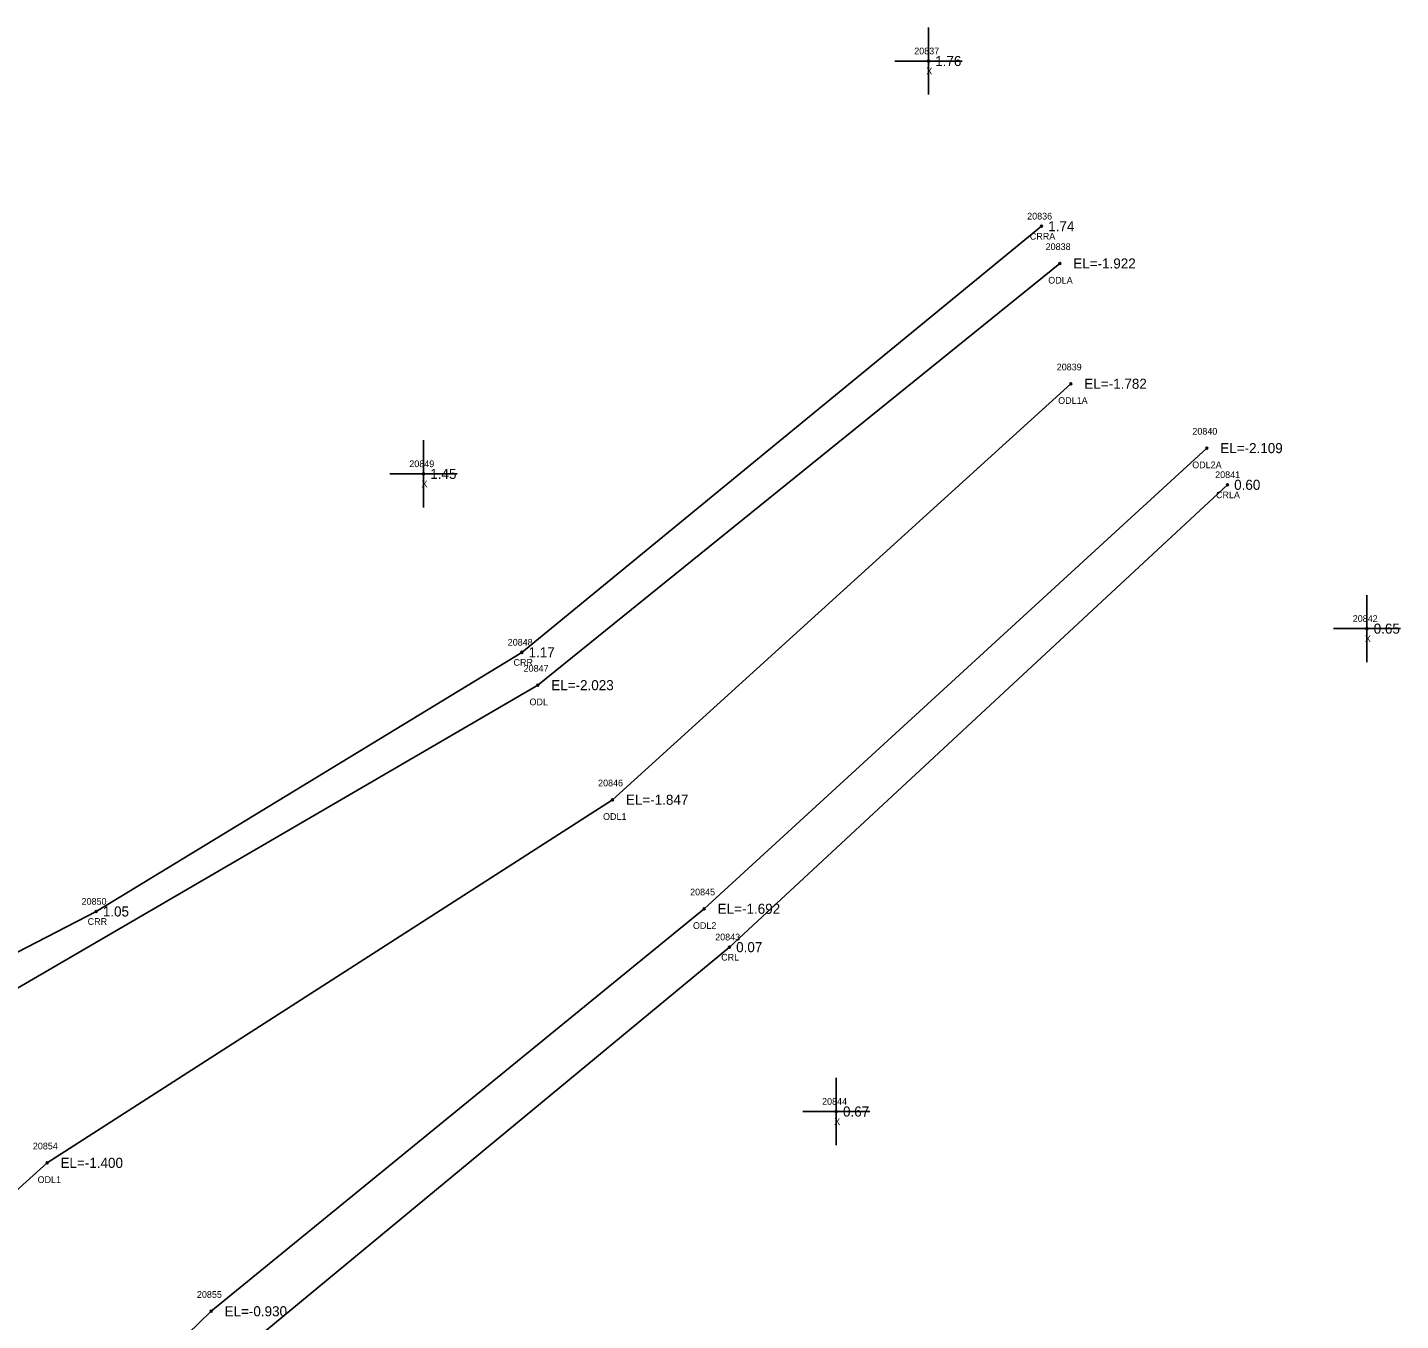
# Model space of a CAD drawing. Extents: x 2608745 to 2610333, y 641917 to 643463.
# Drawn here: x 2609764.9 to 2609969.6, y 642851.5 to 643044.2 of the extents above; entities that cross this region are included whole.
import ezdxf

# ---------------------------------------------------------------- set-up
doc = ezdxf.new("R2010")
doc.units = 0
for name, color, linetype in [('RD_EX_H2O', 7, 'Continuous'), ('RD_EX_H2O_txCode', 7, 'Continuous'), ('RD_EX_Misc', 7, 'Continuous'), ('RD_EX_Misc_txCode', 7, 'Continuous'), ('RD_EX_TX_H2O_ELEV', 7, 'Continuous'), ('RD_EX_TX_Misc_ELEV', 7, 'Continuous'), ('RD_SMD_Locator', 7, 'Continuous')]:
    doc.layers.add(name, color=color, linetype=linetype)

msp = doc.modelspace()

# ---------------------------------------------------------------- linework, layer by layer
at = {"layer": 'RD_EX_H2O'}
for points in [[(2609916.07, 643014.59), (2609838.61, 642951.08), (2609775.14, 642912.46), (2609751.54, 642900.29), (2609699.49, 642867.34), (2609668.6, 642867.67), (2609610.85, 642947.01)], [(2609918.81, 643009.04), (2609840.99, 642946.19), (2609752.78, 642894.89), (2609679.02, 642833.68), (2609605.53, 642770.83), (2609557.42, 642733.27), (2609539.43, 642701.73), (2609511.68, 642671.53), (2609423.05, 642632.06), (2609369.55, 642600.24), (2609327.57, 642579.96), (2609257.07, 642528.8), (2609194.6, 642443.8), (2609156.56, 642341.27)], [(2609920.46, 642991.11), (2609852.12, 642929.11), (2609767.83, 642874.99), (2609693.3, 642807.6), (2609634.08, 642753.09), (2609556.79, 642686.91), (2609524.97, 642657.54), (2609444.81, 642602.16), (2609373.09, 642552.33), (2609285.68, 642492.71), (2609230.49, 642411.33), (2609205.38, 642280.88)], [(2609940.72, 642981.52), (2609865.8, 642912.86), (2609792.29, 642852.87), (2609723.77, 642786.36), (2609663.25, 642717.18), (2609610.37, 642689.46), (2609581.45, 642670.47), (2609545.26, 642637.18), (2609509.19, 642582.86), (2609482.73, 642569.2), (2609408.72, 642506.3), (2609370.25, 642508.5), (2609327.7, 642455.81), (2609283.83, 642369.21), (2609262.12, 642251.22)], [(2609943.79, 642976.05), (2609869.55, 642907.14), (2609797.73, 642847.7), (2609725.24, 642780.75), (2609667.97, 642714.2), (2609673.28, 642700.22), (2609713.56, 642689.91), (2609733.33, 642661.98), (2609719.28, 642638.68), (2609663.61, 642631.91), (2609659.09, 642626.02), (2609711.84, 642571.44), (2609760.21, 642528.21), (2609792.62, 642516.23), (2609800.76, 642528.12), (2609797.45, 642563.99), (2609816.12, 642605.87)]]:
    msp.add_lwpolyline(points, dxfattribs=at)
at = {"layer": 'RD_EX_Misc'}
for p, q in [((2609899.22, 643034.21), (2609899.22, 643044.21)), ((2609894.22, 643039.21), (2609904.22, 643039.21)), ((2609823.95, 642972.68), (2609823.95, 642982.68)), ((2609818.95, 642977.68), (2609828.95, 642977.68)), ((2609964.59, 642949.61), (2609964.59, 642959.61)), ((2609959.59, 642954.61), (2609969.59, 642954.61)), ((2609885.48, 642877.64), (2609885.48, 642887.64)), ((2609880.48, 642882.64), (2609890.48, 642882.64))]:
    msp.add_line(p, q, dxfattribs=at)
at = {"layer": 'RD_SMD_Locator'}
for centre in [(2609899.22, 643039.21), (2609916.07, 643014.59), (2609918.81, 643009.04), (2609920.46, 642991.11), (2609940.72, 642981.52), (2609823.95, 642977.68), (2609943.79, 642976.05), (2609964.59, 642954.61), (2609838.61, 642951.08), (2609840.99, 642946.19), (2609852.12, 642929.11), (2609775.14, 642912.46), (2609865.8, 642912.86), (2609869.55, 642907.14), (2609885.48, 642882.64), (2609767.83, 642874.99), (2609792.29, 642852.87)]:
    msp.add_circle(centre, 0.15, dxfattribs=at)

# ---------------------------------------------------------------- texts
at = {"layer": 'RD_EX_H2O_txCode'}
for s, p in [('20836', (2609913.93, 643015.59)), ('CRRA', (2609914.33, 643012.59)), ('20838', (2609916.69, 643011.04)), ('ODLA', (2609917.08, 643006.04)), ('20839', (2609918.34, 642993.11)), ('ODL1A', (2609918.56, 642988.11)), ('20840', (2609938.56, 642983.52)), ('ODL2A', (2609938.54, 642978.52)), ('20841', (2609941.96, 642977.05)), ('CRLA', (2609942.08, 642974.05)), ('20848', (2609836.5, 642952.08)), ('CRR', (2609837.36, 642949.08)), ('20847', (2609838.87, 642948.19)), ('ODL', (2609839.75, 642943.19)), ('20846', (2609849.97, 642931.11)), ('ODL1', (2609850.71, 642926.11)), ('20845', (2609863.69, 642914.86)), ('20850', (2609772.98, 642913.46)), ('CRR', (2609773.88, 642910.46)), ('ODL2', (2609864.11, 642909.86)), ('20843', (2609867.43, 642908.14)), ('CRL', (2609868.32, 642905.14)), ('20854', (2609765.71, 642876.99)), ('ODL1', (2609766.42, 642871.99)), ('20855', (2609790.17, 642854.87))]:
    msp.add_text(s, height=1, dxfattribs=at).set_placement(p)
at = {"layer": 'RD_EX_Misc_txCode'}
for s, p in [('20837', (2609897.1, 643040.21)), ('X', (2609898.9, 643037.21)), ('20849', (2609821.83, 642978.68)), ('X', (2609823.64, 642975.68)), ('20842', (2609962.47, 642955.61)), ('X', (2609964.28, 642952.61)), ('20844', (2609883.36, 642883.64)), ('X', (2609885.17, 642880.64))]:
    msp.add_text(s, height=1, dxfattribs=at).set_placement(p)
at = {"layer": 'RD_EX_TX_H2O_ELEV'}
for s, p in [('1.74', (2609917.07, 643013.84)), ('EL=-1.922', (2609920.81, 643008.29)), ('EL=-1.782', (2609922.46, 642990.36)), ('EL=-2.109', (2609942.72, 642980.77)), ('0.60', (2609944.79, 642975.3)), ('1.17', (2609839.61, 642950.33)), ('EL=-2.023', (2609842.99, 642945.44)), ('EL=-1.847', (2609854.12, 642928.36)), ('1.05', (2609776.14, 642911.71)), ('EL=-1.692', (2609867.8, 642912.11)), ('0.07', (2609870.55, 642906.39)), ('EL=-1.400', (2609769.83, 642874.24)), ('EL=-0.930', (2609794.29, 642852.12))]:
    msp.add_text(s, height=1.5, dxfattribs=at).set_placement(p)
at = {"layer": 'RD_EX_TX_Misc_ELEV'}
for s, p in [('1.76', (2609900.22, 643038.46)), ('1.45', (2609824.95, 642976.93)), ('0.65', (2609965.59, 642953.86)), ('0.67', (2609886.48, 642881.89))]:
    msp.add_text(s, height=1.5, dxfattribs=at).set_placement(p)

doc.saveas('drawing.dxf')
